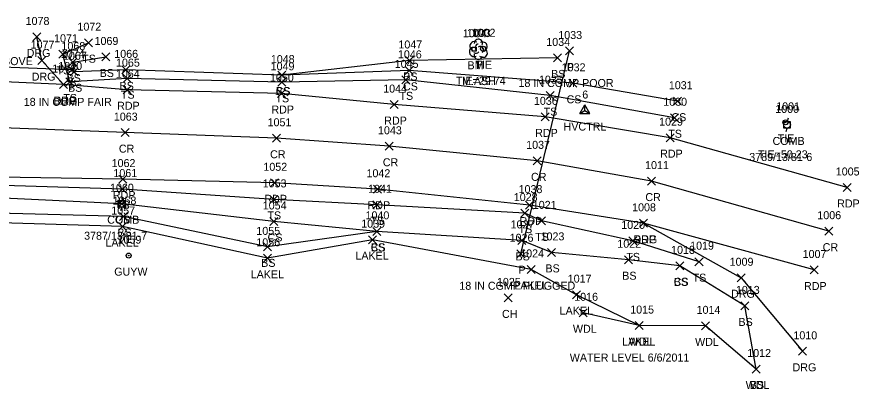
# Model space of a CAD drawing. Extents: x 1401404 to 1403982, y 557481 to 559873.
# Drawn here: x 1403540.8 to 1403751.4, y 558518.6 to 558611.7 of the extents above; entities that cross this region are included whole.
import ezdxf

# ---------------------------------------------------------------- set-up
doc = ezdxf.new("R2010")
doc.units = 0
for name, color, linetype in [('C_A', 7, 'Continuous'), ('C_C', 7, 'Continuous'), ('C_I', 7, 'Continuous'), ('CBP', 7, 'Continuous'), ('CPBM', 7, 'Continuous'), ('CPSM', 7, 'Continuous'), ('D_A', 7, 'Continuous'), ('D_C', 7, 'Continuous'), ('D_I', 7, 'Continuous'), ('D_TIC', 7, 'Continuous'), ('DCP', 7, 'Continuous'), ('L_A', 7, 'Continuous'), ('L_C', 7, 'Continuous'), ('L_I', 7, 'Continuous'), ('L_TIC', 7, 'Continuous'), ('LAWA', 7, 'Continuous'), ('LAWE', 7, 'Continuous'), ('LELB', 7, 'Continuous'), ('LTD', 7, 'Continuous'), ('M_C', 7, 'Continuous'), ('P_A', 7, 'Continuous'), ('P_I', 7, 'Continuous'), ('P_TIC', 7, 'Continuous'), ('PET', 7, 'Continuous'), ('PRC', 7, 'Continuous'), ('R_A', 7, 'Continuous'), ('R_I', 7, 'Continuous'), ('R_TIC', 7, 'Continuous'), ('RDG', 7, 'Continuous'), ('U_A', 7, 'Continuous'), ('U_C', 7, 'Continuous'), ('U_I', 7, 'Continuous'), ('UP', 7, 'Continuous'), ('UPGW', 7, 'Continuous')]:
    doc.layers.add(name, color=color, linetype=linetype)

msp = doc.modelspace()

# ---------------------------------------------------------------- linework, layer by layer
at = {"layer": 'CBP'}
for centre, radius in [((1403657.34, 558603.74), 0.625), ((1403657.34, 558603.74), 0.0833), ((1403732.91, 558585.34), 0.625), ((1403732.91, 558585.34), 0.0833)]:
    msp.add_circle(centre, radius, dxfattribs=at)
at = {"layer": 'CPBM'}
for p, q in [((1403654.63, 558603.11), (1403654.63, 558604.11)), ((1403654.63, 558604.11), (1403655.63, 558604.11)), ((1403655.63, 558604.11), (1403655.63, 558603.11)), ((1403655.63, 558603.11), (1403654.63, 558603.11)), ((1403655.13, 558603.61), (1403655.13, 558603.61)), ((1403655.13, 558603.61), (1403655.13, 558603.61))]:
    msp.add_line(p, q, dxfattribs=at)
at = {"layer": 'CPSM'}
for p, q in [((1403681.51, 558587.57), (1403682.76, 558589.73)), ((1403684.01, 558587.57), (1403682.76, 558589.73)), ((1403682.76, 558588.29), (1403682.76, 558589.73)), ((1403681.51, 558587.57), (1403682.76, 558588.29)), ((1403681.51, 558587.57), (1403684.01, 558587.57)), ((1403682.76, 558588.29), (1403682.76, 558588.29)), ((1403682.76, 558588.29), (1403684.01, 558587.57))]:
    msp.add_line(p, q, dxfattribs=at)
at = {"layer": 'D_TIC'}
for points in [[(1403677.92, 558602.18), (1403679.92, 558604.18)], [(1403679.92, 558602.18), (1403677.92, 558604.18)], [(1403553.56, 558597.47), (1403555.56, 558599.47)], [(1403555.56, 558597.47), (1403553.56, 558599.47)], [(1403665.82, 558551.49), (1403667.82, 558553.49)], [(1403667.82, 558551.49), (1403665.82, 558553.49)]]:
    msp.add_lwpolyline(points, dxfattribs=at)
at = {"layer": 'DCP'}
for points in [[(1403666.82, 558552.49), (1403678.92, 558603.18)], [(1403554.56, 558598.47), (1403524.07, 558599.63)]]:
    msp.add_lwpolyline(points, dxfattribs=at)
at = {"layer": 'L_TIC'}
for points in [[(1403557.72, 558604.26), (1403559.72, 558606.26)], [(1403559.72, 558604.26), (1403557.72, 558606.26)], [(1403551.31, 558601.35), (1403553.31, 558603.35)], [(1403553.31, 558601.35), (1403551.31, 558603.35)], [(1403562.06, 558600.69), (1403564.06, 558602.69)], [(1403564.06, 558600.69), (1403562.06, 558602.69)], [(1403674.92, 558600.45), (1403676.92, 558602.45)], [(1403676.92, 558600.45), (1403674.92, 558602.45)], [(1403553.78, 558599.42), (1403555.78, 558601.42)], [(1403555.78, 558599.42), (1403553.78, 558601.42)], [(1403637.96, 558599.81), (1403639.96, 558601.81)], [(1403639.96, 558599.81), (1403637.96, 558601.81)], [(1403554.16, 558596.98), (1403556.16, 558598.98)], [(1403556.16, 558596.98), (1403554.16, 558598.98)], [(1403567.04, 558597.47), (1403569.04, 558599.47)], [(1403569.04, 558597.47), (1403567.04, 558599.47)], [(1403606.07, 558596.15), (1403608.07, 558598.15)], [(1403608.07, 558596.15), (1403606.07, 558598.15)], [(1403606.07, 558596.15), (1403608.07, 558598.15)], [(1403608.07, 558596.15), (1403606.07, 558598.15)], [(1403637.89, 558597.34), (1403639.89, 558599.34)], [(1403639.89, 558597.34), (1403637.89, 558599.34)], [(1403553.02, 558594.44), (1403555.02, 558596.44)], [(1403555.02, 558594.44), (1403553.02, 558596.44)], [(1403567.41, 558595.27), (1403569.41, 558597.27)], [(1403569.41, 558595.27), (1403567.41, 558597.27)], [(1403606.03, 558594.36), (1403608.03, 558596.36)], [(1403608.03, 558594.36), (1403606.03, 558596.36)], [(1403637.03, 558594.97), (1403639.03, 558596.97)], [(1403639.03, 558594.97), (1403637.03, 558596.97)], [(1403678.77, 558594.1), (1403680.77, 558596.1)], [(1403680.77, 558594.1), (1403678.77, 558596.1)], [(1403673.08, 558591.02), (1403675.08, 558593.02)], [(1403675.08, 558591.02), (1403673.08, 558593.02)], [(1403704.98, 558589.63), (1403706.98, 558591.63)], [(1403706.98, 558589.63), (1403704.98, 558591.63)], [(1403704.23, 558585.49), (1403706.23, 558587.49)], [(1403706.23, 558585.49), (1403704.23, 558587.49)], [(1403566.19, 558567.67), (1403568.19, 558569.67)], [(1403568.19, 558567.67), (1403566.19, 558569.67)], [(1403604.03, 558565.08), (1403606.03, 558567.08)], [(1403606.03, 558565.08), (1403604.03, 558567.08)], [(1403566.01, 558564), (1403568.01, 558566)], [(1403568.01, 558564), (1403566.01, 558566)], [(1403629.8, 558563.73), (1403631.8, 558565.73)], [(1403631.8, 558563.73), (1403629.8, 558565.73)], [(1403566.5, 558560.8), (1403568.5, 558562.8)], [(1403568.5, 558560.8), (1403566.5, 558562.8)], [(1403666.8, 558561.66), (1403668.8, 558563.66)], [(1403668.8, 558561.66), (1403666.8, 558563.66)], [(1403566.18, 558558.29), (1403568.18, 558560.29)], [(1403568.18, 558558.29), (1403566.18, 558560.29)], [(1403604.04, 558559.57), (1403606.04, 558561.57)], [(1403606.04, 558559.57), (1403604.04, 558561.57)], [(1403670.97, 558559.71), (1403672.97, 558561.71)], [(1403672.97, 558559.71), (1403670.97, 558561.71)], [(1403629.82, 558557.09), (1403631.82, 558559.09)], [(1403631.82, 558557.09), (1403629.82, 558559.09)], [(1403629.82, 558557.09), (1403631.82, 558559.09)], [(1403631.82, 558557.09), (1403629.82, 558559.09)], [(1403628.67, 558555.01), (1403630.67, 558557.01)], [(1403630.67, 558555.01), (1403628.67, 558557.01)], [(1403666, 558554.83), (1403668, 558556.83)], [(1403668, 558554.83), (1403666, 558556.83)], [(1403693.74, 558554.7), (1403695.74, 558556.7)], [(1403695.74, 558554.7), (1403693.74, 558556.7)], [(1403602.44, 558553.21), (1403604.44, 558555.21)], [(1403604.44, 558553.21), (1403602.44, 558555.21)], [(1403673.49, 558551.83), (1403675.49, 558553.83)], [(1403675.49, 558551.83), (1403673.49, 558553.83)], [(1403602.5, 558550.35), (1403604.5, 558552.35)], [(1403604.5, 558550.35), (1403602.5, 558552.35)], [(1403692.69, 558550), (1403694.69, 558552)], [(1403694.69, 558550), (1403692.69, 558552)], [(1403710.32, 558549.51), (1403712.32, 558551.51)], [(1403712.32, 558549.51), (1403710.32, 558551.51)], [(1403668.4, 558547.58), (1403670.4, 558549.58)], [(1403670.4, 558547.58), (1403668.4, 558549.58)], [(1403705.56, 558548.47), (1403707.56, 558550.47)], [(1403707.56, 558548.47), (1403705.56, 558550.47)], [(1403705.56, 558548.47), (1403707.56, 558550.47)], [(1403707.56, 558548.47), (1403705.56, 558550.47)], [(1403679.72, 558541.26), (1403681.72, 558543.26)], [(1403681.72, 558541.26), (1403679.72, 558543.26)], [(1403662.59, 558540.45), (1403664.59, 558542.45)], [(1403664.59, 558540.45), (1403662.59, 558542.45)], [(1403681.39, 558536.73), (1403683.39, 558538.73)], [(1403683.39, 558536.73), (1403681.39, 558538.73)], [(1403721.74, 558538.45), (1403723.74, 558540.45)], [(1403723.74, 558538.45), (1403721.74, 558540.45)], [(1403695.34, 558533.54), (1403697.34, 558535.54)], [(1403697.34, 558533.54), (1403695.34, 558535.54)], [(1403695.34, 558533.54), (1403697.34, 558535.54)], [(1403697.34, 558533.54), (1403695.34, 558535.54)], [(1403711.93, 558533.47), (1403713.93, 558535.47)], [(1403713.93, 558533.47), (1403711.93, 558535.47)], [(1403724.58, 558522.67), (1403726.58, 558524.67)], [(1403726.58, 558522.67), (1403724.58, 558524.67)], [(1403724.58, 558522.67), (1403726.58, 558524.67)], [(1403726.58, 558522.67), (1403724.58, 558524.67)]]:
    msp.add_lwpolyline(points, dxfattribs=at)
at = {"layer": 'LAWA'}
msp.add_lwpolyline([(1403725.58, 558523.67), (1403712.93, 558534.47), (1403696.34, 558534.54), (1403682.39, 558537.73)], dxfattribs=at)
at = {"layer": 'LAWE'}
msp.add_lwpolyline([(1403696.34, 558534.54), (1403680.72, 558542.26), (1403669.4, 558548.58), (1403629.67, 558556.01), (1403603.5, 558551.35), (1403567.18, 558559.29), (1403520.13, 558560.76), (1403486.9, 558558.65), (1403434.25, 558550.99), (1403410.67, 558547.97), (1403397.83, 558540.52), (1403383.21, 558537.84), (1403361.63, 558542.24), (1403347.73, 558548.91), (1403330.86, 558557.2), (1403312.09, 558569.67), (1403266.36, 558595.5), (1403259.7, 558589.6), (1403257.9, 558590.94)], dxfattribs=at)
at = {"layer": 'LELB'}
for points in [[(1403705.23, 558586.49), (1403674.08, 558592.02), (1403638.03, 558595.97), (1403607.03, 558595.36), (1403568.41, 558596.27), (1403554.02, 558595.44), (1403552.31, 558602.35), (1403558.72, 558605.26)], [(1403675.92, 558601.45), (1403638.96, 558600.81), (1403607.07, 558597.15), (1403568.04, 558598.47), (1403555.16, 558597.98), (1403554.78, 558600.42), (1403563.06, 558601.69)], [(1403705.98, 558590.63), (1403679.77, 558595.1), (1403638.89, 558598.34), (1403607.07, 558597.15)], [(1403630.82, 558558.09), (1403605.04, 558560.57), (1403567.01, 558565), (1403521.82, 558567.1), (1403485.28, 558566.39), (1403436.65, 558571.38), (1403404.16, 558574.1), (1403374.76, 558578.32), (1403361.78, 558581.54), (1403361.26, 558576.4), (1403370.54, 558575)], [(1403725.58, 558523.67), (1403722.74, 558539.45), (1403706.56, 558549.47), (1403693.69, 558551), (1403674.49, 558552.83), (1403667, 558555.83), (1403630.82, 558558.09), (1403603.44, 558554.21), (1403567.5, 558561.8), (1403520.15, 558563.09), (1403486.24, 558561.72), (1403436.49, 558562.32), (1403409.67, 558557.93), (1403401.43, 558554.22), (1403392.6, 558552.11), (1403381.98, 558552.19), (1403374.37, 558554.61), (1403368.01, 558558.84), (1403339.85, 558573.14), (1403322.98, 558578.01)], [(1403711.32, 558550.51), (1403694.74, 558555.7), (1403671.97, 558560.71), (1403667.8, 558562.66), (1403630.8, 558564.73), (1403605.03, 558566.08), (1403567.19, 558568.67), (1403521.33, 558570.05)]]:
    msp.add_lwpolyline(points, dxfattribs=at)
at = {"layer": 'LTD'}
msp.add_line((1403656.14, 558603.66), (1403656.14, 558603.66), dxfattribs=at)
msp.add_line((1403656.14, 558603.66), (1403656.14, 558603.66), dxfattribs=at)
msp.add_arc((1403656.19, 558605.09), 1.05, 335.5272, 180.9563, dxfattribs=at)
for centre, major_axis, ratio, start_param, end_param in [((1403655.06, 558602.95), (0.58, -1.04), 0.959034, 3.141593, 6.283185), ((1403655.35, 558604.32), (1.21, -0.51), 0.895232, 1.570796, 4.712389), ((1403655.93, 558604.12), (-0.208, -0.792), 0.645439, 3.141593, 6.283185), ((1403656.64, 558603.49), (-0.5, 0.667), 0.989748, 3.141593, 6.283185), ((1403657.18, 558604.24), (-1.14, -0.48), 0.949671, 1.570796, 4.712389), ((1403656.14, 558602.16), (0.26, 1.06), 0.942809, 1.570796, 4.712389), ((1403655.68, 558602.91), (-0.625, -0.083), 0.423636, 0, 3.141593), ((1403657.14, 558602.82), (-1.09, 0.79), 0.841452, 1.570796, 4.712389)]:
    msp.add_ellipse(centre, major_axis=major_axis, ratio=ratio, start_param=start_param, end_param=end_param, dxfattribs=at)
at = {"layer": 'P_TIC'}
for points in [[(1403551.49, 558593.8), (1403553.49, 558595.8)], [(1403553.49, 558593.8), (1403551.49, 558595.8)], [(1403567.39, 558592.49), (1403569.39, 558594.49)], [(1403569.39, 558592.49), (1403567.39, 558594.49)], [(1403605.94, 558591.55), (1403607.94, 558593.55)], [(1403607.94, 558591.55), (1403605.94, 558593.55)], [(1403634.15, 558588.78), (1403636.15, 558590.78)], [(1403636.15, 558588.78), (1403634.15, 558590.78)], [(1403671.88, 558585.72), (1403673.88, 558587.72)], [(1403673.88, 558585.72), (1403671.88, 558587.72)], [(1403566.87, 558581.77), (1403568.87, 558583.77)], [(1403568.87, 558581.77), (1403566.87, 558583.77)], [(1403604.68, 558580.36), (1403606.68, 558582.36)], [(1403606.68, 558580.36), (1403604.68, 558582.36)], [(1403703.13, 558580.51), (1403705.13, 558582.51)], [(1403705.13, 558580.51), (1403703.13, 558582.51)], [(1403632.86, 558578.36), (1403634.86, 558580.36)], [(1403634.86, 558578.36), (1403632.86, 558580.36)], [(1403669.89, 558574.72), (1403671.89, 558576.72)], [(1403671.89, 558574.72), (1403669.89, 558576.72)], [(1403566.32, 558570.16), (1403568.32, 558572.16)], [(1403568.32, 558570.16), (1403566.32, 558572.16)], [(1403604.2, 558569.23), (1403606.2, 558571.23)], [(1403606.2, 558569.23), (1403604.2, 558571.23)], [(1403698.47, 558569.66), (1403700.47, 558571.66)], [(1403700.47, 558569.66), (1403698.47, 558571.66)], [(1403629.98, 558567.62), (1403631.98, 558569.62)], [(1403631.98, 558567.62), (1403629.98, 558569.62)], [(1403747.36, 558568.06), (1403749.36, 558570.06)], [(1403749.36, 558568.06), (1403747.36, 558570.06)], [(1403667.99, 558563.64), (1403669.99, 558565.64)], [(1403669.99, 558563.64), (1403667.99, 558565.64)], [(1403696.45, 558559.1), (1403698.45, 558561.1)], [(1403698.45, 558559.1), (1403696.45, 558561.1)], [(1403742.81, 558557.13), (1403744.81, 558559.13)], [(1403744.81, 558557.13), (1403742.81, 558559.13)], [(1403739.08, 558547.43), (1403741.08, 558549.43)], [(1403741.08, 558547.43), (1403739.08, 558549.43)]]:
    msp.add_lwpolyline(points, dxfattribs=at)
at = {"layer": 'PET'}
for points in [[(1403748.36, 558569.06), (1403704.13, 558581.51), (1403672.88, 558586.72), (1403635.15, 558589.78), (1403606.94, 558592.55), (1403568.39, 558593.49), (1403552.49, 558594.8), (1403524.49, 558596.02)], [(1403740.08, 558548.43), (1403697.45, 558560.1), (1403668.99, 558564.64), (1403630.98, 558568.62), (1403605.2, 558570.23), (1403567.32, 558571.16), (1403521.05, 558571.89)]]:
    msp.add_lwpolyline(points, dxfattribs=at)
at = {"layer": 'PRC'}
msp.add_lwpolyline([(1403743.81, 558558.13), (1403699.47, 558570.66), (1403670.89, 558575.72), (1403633.86, 558579.36), (1403605.68, 558581.36), (1403567.87, 558582.77), (1403521.72, 558584.55)], dxfattribs=at)
at = {"layer": 'R_TIC'}
for points in [[(1403544.77, 558605.69), (1403546.77, 558607.69)], [(1403546.77, 558605.69), (1403544.77, 558607.69)], [(1403546.03, 558599.77), (1403548.03, 558601.77)], [(1403548.03, 558599.77), (1403546.03, 558601.77)], [(1403551.49, 558593.8), (1403553.49, 558595.8)], [(1403553.49, 558593.8), (1403551.49, 558595.8)], [(1403696.45, 558559.1), (1403698.45, 558561.1)], [(1403698.45, 558559.1), (1403696.45, 558561.1)], [(1403720.84, 558545.49), (1403722.84, 558547.49)], [(1403722.84, 558545.49), (1403720.84, 558547.49)], [(1403736.21, 558527.1), (1403738.21, 558529.1)], [(1403738.21, 558527.1), (1403736.21, 558529.1)]]:
    msp.add_lwpolyline(points, dxfattribs=at)
at = {"layer": 'RDG'}
for points in [[(1403552.49, 558594.8), (1403547.03, 558600.77), (1403545.77, 558606.69)], [(1403697.45, 558560.1), (1403721.84, 558546.49), (1403737.21, 558528.1)]]:
    msp.add_lwpolyline(points, dxfattribs=at)
at = {"layer": 'UP'}
for p, q in [((1403732.49, 558583.86), (1403732.49, 558585.53)), ((1403732.49, 558585.53), (1403734.15, 558585.53)), ((1403733.57, 558586.36), (1403733.32, 558585.53)), ((1403734.15, 558585.53), (1403734.15, 558583.86)), ((1403734.15, 558583.86), (1403732.49, 558583.86)), ((1403733.07, 558583.03), (1403733.32, 558583.86)), ((1403733.32, 558584.69), (1403733.32, 558584.69)), ((1403567.26, 558566.67), (1403567.01, 558565.84)), ((1403566.17, 558564.17), (1403566.17, 558565.84)), ((1403566.17, 558565.84), (1403567.84, 558565.84)), ((1403567.84, 558564.17), (1403566.17, 558564.17)), ((1403566.76, 558563.34), (1403567.01, 558564.17)), ((1403567.01, 558565), (1403567.01, 558565)), ((1403567.84, 558565.84), (1403567.84, 558564.17))]:
    msp.add_line(p, q, dxfattribs=at)
for centre in [(1403733.32, 558584.69), (1403567.01, 558565)]:
    msp.add_circle(centre, 0.833, dxfattribs=at)
at = {"layer": 'UPGW'}
for radius in [0.625, 0.0833]:
    msp.add_circle((1403568.76, 558552.02), radius, dxfattribs=at)

# ---------------------------------------------------------------- texts
at = {"layer": 'C_A'}
for s, p in [('BM', (1403653.45, 558598.61)), ('TIE', (1403655.42, 558598.74)), ('HVCTRL', (1403677.46, 558583.29)), ('TIE', (1403730.98, 558580.34))]:
    msp.add_text(s, height=2, dxfattribs=at).set_placement(p)
at = {"layer": 'C_C'}
for s, p in [('TIE=29.74', (1403650.57, 558594.74)), ('TIE=50.23', (1403726.06, 558576.34))]:
    msp.add_text(s, height=2, dxfattribs=at).set_placement(p)
at = {"layer": 'C_I'}
for s, p in [('1004', (1403652.28, 558606.61)), ('1002', (1403654.49, 558606.74)), ('6', (1403682.14, 558591.29)), ('1001', (1403730.62, 558588.34))]:
    msp.add_text(s, height=2, dxfattribs=at).set_placement(p)
at = {"layer": 'D_A'}
for p in [(1403678.3, 558598.18), (1403553.93, 558593.47), (1403666.2, 558547.49)]:
    msp.add_text('P', height=2, dxfattribs=at).set_placement(p)
at = {"layer": 'D_C'}
for s, p in [('18 IN CGMP POOR', (1403666.2, 558594.18)), ('18 IN CGMP FAIR', (1403542.53, 558589.47)), ('18 IN CGMP PLUGGED', (1403651.41, 558543.49))]:
    msp.add_text(s, height=2, dxfattribs=at).set_placement(p)
at = {"layer": 'D_I'}
for s, p in [('1033', (1403676.15, 558606.18)), ('1074', (1403551.78, 558601.47)), ('1026', (1403663.99, 558555.49))]:
    msp.add_text(s, height=2, dxfattribs=at).set_placement(p)
at = {"layer": 'L_A'}
for s, p in [('TS', (1403557.13, 558600.26)), ('H', (1403655.57, 558598.66)), ('TS', (1403550.72, 558597.35)), ('BS', (1403561.5, 558596.69)), ('BS', (1403637.4, 558595.81)), ('BS', (1403674.36, 558596.45)), ('BS', (1403553.22, 558595.42)), ('BS', (1403553.6, 558592.98)), ('BS', (1403566.48, 558593.47)), ('CS', (1403605.51, 558592.15)), ('BS', (1403605.51, 558592.15)), ('CS', (1403637.33, 558593.34)), ('TS', (1403552.43, 558590.44)), ('TS', (1403566.82, 558591.27)), ('TS', (1403605.44, 558590.36)), ('TS', (1403636.44, 558590.97)), ('CS', (1403678.22, 558590.1)), ('TS', (1403672.49, 558587.02)), ('CS', (1403704.43, 558585.63)), ('TS', (1403703.64, 558581.49)), ('TS', (1403565.6, 558563.67)), ('CS', (1403565.45, 558560)), ('TS', (1403603.44, 558561.08)), ('TS', (1403629.21, 558559.73)), ('BS', (1403565.94, 558556.8)), ('TS', (1403666.21, 558557.66)), ('TS', (1403670.38, 558555.71)), ('LAKEL', (1403562.95, 558554.29)), ('CS', (1403603.48, 558555.57)), ('CS', (1403629.26, 558553.09)), ('BS', (1403629.26, 558553.09)), ('LAKEL', (1403625.43, 558551.01)), ('BS', (1403665.44, 558550.83)), ('TS', (1403693.15, 558550.7)), ('BS', (1403601.88, 558549.21)), ('BS', (1403672.93, 558547.83)), ('LAKEL', (1403599.26, 558546.35)), ('BS', (1403692.13, 558546)), ('TS', (1403709.73, 558545.51)), ('LAKEL', (1403665.17, 558543.58)), ('CS', (1403705, 558544.47)), ('BS', (1403705, 558544.47)), ('LAKEL', (1403676.48, 558537.26)), ('CH', (1403662.07, 558536.45)), ('WDL', (1403679.8, 558532.73)), ('BS', (1403721.18, 558534.45)), ('LAKEL', (1403692.1, 558529.54)), ('WDL', (1403693.76, 558529.54)), ('WDL', (1403710.34, 558529.47)), ('WDL', (1403722.99, 558518.67)), ('BS', (1403724.02, 558518.67))]:
    msp.add_text(s, height=2, dxfattribs=at).set_placement(p)
at = {"layer": 'L_C'}
for s, p in [('M.ASH', (1403652.09, 558594.66)), ('WATER LEVEL 6/6/2011', (1403679.02, 558525.54))]:
    msp.add_text(s, height=2, dxfattribs=at).set_placement(p)
at = {"layer": 'L_I'}
for s, p in [('1072', (1403555.95, 558608.26)), ('1003', (1403653.29, 558606.66)), ('1071', (1403550.11, 558605.35)), ('1069', (1403560.23, 558604.69)), ('1034', (1403673.15, 558604.45)), ('1068', (1403551.96, 558603.42)), ('1047', (1403636.18, 558603.81)), ('1067', (1403552.34, 558600.98)), ('1066', (1403565.16, 558601.47)), ('1048', (1403604.29, 558600.15)), ('1048', (1403604.29, 558600.15)), ('1046', (1403636.06, 558601.34)), ('1070', (1403551.17, 558598.44)), ('1065', (1403565.59, 558599.27)), ('1049', (1403604.25, 558598.36)), ('1045', (1403635.26, 558598.97)), ('1032', (1403677, 558598.1)), ('1035', (1403671.31, 558595.02)), ('1031', (1403703.78, 558593.63)), ('1030', (1403702.38, 558589.49)), ('1061', (1403564.94, 558571.67)), ('1053', (1403602.26, 558569.08)), ('1060', (1403564.1, 558568)), ('1041', (1403628.6, 558567.73)), ('1058', (1403564.73, 558564.8)), ('1028', (1403665.02, 558565.66)), ('1057', (1403564.41, 558562.29)), ('1054', (1403602.27, 558563.57)), ('1021', (1403669.77, 558563.71)), ('1040', (1403627.96, 558561.09)), ('1040', (1403627.96, 558561.09)), ('1039', (1403626.89, 558559.01)), ('1027', (1403664.23, 558558.83)), ('1020', (1403691.89, 558558.7)), ('1055', (1403600.67, 558557.21)), ('1023', (1403671.72, 558555.83)), ('1056', (1403600.67, 558554.35)), ('1022', (1403690.91, 558554)), ('1019', (1403709.11, 558553.51)), ('1024', (1403666.63, 558551.58)), ('1018', (1403704.35, 558552.47)), ('1018', (1403704.35, 558552.47)), ('1017', (1403678.51, 558545.26)), ('1025', (1403660.81, 558544.45)), ('1013', (1403720.54, 558542.45)), ('1016', (1403680.13, 558540.73)), ('1015', (1403694.13, 558537.54)), ('1015', (1403694.13, 558537.54)), ('1014', (1403710.72, 558537.47)), ('1012', (1403723.37, 558526.67)), ('1012', (1403723.37, 558526.67))]:
    msp.add_text(s, height=2, dxfattribs=at).set_placement(p)
at = {"layer": 'M_C'}
msp.add_text('DBS ZT LS623 REBAR 1 FT ABOVE', height=2, dxfattribs=at).set_placement((1403500.65, 558599.65))
at = {"layer": 'P_A'}
for s, p in [('RDP', (1403549.98, 558589.8)), ('RDP', (1403565.87, 558588.49)), ('RDP', (1403604.43, 558587.55)), ('RDP', (1403632.64, 558584.78)), ('RDP', (1403670.37, 558581.72)), ('CR', (1403566.31, 558577.77)), ('CR', (1403604.11, 558576.36)), ('RDP', (1403701.61, 558576.51)), ('CR', (1403632.29, 558574.36)), ('CR', (1403669.33, 558570.72)), ('RDP', (1403564.81, 558566.16)), ('RDP', (1403602.69, 558565.23)), ('CR', (1403697.91, 558565.66)), ('RDP', (1403745.85, 558564.06)), ('RDP', (1403628.47, 558563.62)), ('RDP', (1403666.48, 558559.64)), ('RDP', (1403694.94, 558555.1)), ('CR', (1403742.24, 558553.13)), ('RDP', (1403737.57, 558543.43))]:
    msp.add_text(s, height=2, dxfattribs=at).set_placement(p)
at = {"layer": 'P_I'}
for s, p in [('1076', (1403549.66, 558597.8)), ('1064', (1403565.57, 558596.49)), ('1050', (1403604.08, 558595.55)), ('1044', (1403632.38, 558592.78)), ('1036', (1403670.05, 558589.72)), ('1063', (1403565.05, 558585.77)), ('1051', (1403603.48, 558584.36)), ('1029', (1403701.35, 558584.51)), ('1043', (1403631.08, 558582.36)), ('1037', (1403668.12, 558578.72)), ('1062', (1403564.5, 558574.16)), ('1052', (1403602.43, 558573.23)), ('1011', (1403697.84, 558573.66)), ('1042', (1403628.21, 558571.62)), ('1005', (1403745.51, 558572.06)), ('1038', (1403666.22, 558567.64)), ('1008', (1403694.6, 558563.1)), ('1006', (1403740.9, 558561.13)), ('1007', (1403737.23, 558551.43))]:
    msp.add_text(s, height=2, dxfattribs=at).set_placement(p)
at = {"layer": 'R_A'}
for p in [(1403543.26, 558601.69), (1403544.52, 558595.77), (1403549.98, 558589.8), (1403694.94, 558555.1), (1403719.33, 558541.49), (1403734.7, 558523.1)]:
    msp.add_text('DRG', height=2, dxfattribs=at).set_placement(p)
at = {"layer": 'R_I'}
for s, p in [('1078', (1403543, 558609.69)), ('1077', (1403544.26, 558603.77)), ('1076', (1403549.66, 558597.8)), ('1008', (1403694.6, 558563.1)), ('1009', (1403718.98, 558549.49)), ('1010', (1403734.92, 558531.1))]:
    msp.add_text(s, height=2, dxfattribs=at).set_placement(p)
at = {"layer": 'U_A'}
for s, p in [('COMB', (1403729.71, 558579.69)), ('COMB', (1403563.39, 558560)), ('GUYW', (1403565.15, 558547.02))]:
    msp.add_text(s, height=2, dxfattribs=at).set_placement(p)
at = {"layer": 'U_C'}
for s, p in [('3789/13/81-6', (1403723.88, 558575.69)), ('3787/13/81-7', (1403557.62, 558556))]:
    msp.add_text(s, height=2, dxfattribs=at).set_placement(p)
at = {"layer": 'U_I'}
for s, p in [('1000', (1403730.38, 558587.69)), ('1060', (1403564.1, 558568)), ('1059', (1403565.98, 558555.02))]:
    msp.add_text(s, height=2, dxfattribs=at).set_placement(p)

doc.saveas('drawing.dxf')
